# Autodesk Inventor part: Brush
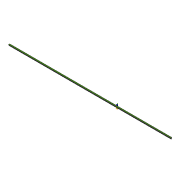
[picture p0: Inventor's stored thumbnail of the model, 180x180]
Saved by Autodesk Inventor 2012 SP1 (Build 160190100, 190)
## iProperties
Created: 2006-03
Part Number: Brush
Document SubType Name: Modeling
Material: Silicone
Mass: 8.74327 g
Surface Area: 94.4143 cm^2
Volume: 6.99461 cm^3
Density: 1.25 g/cm^3
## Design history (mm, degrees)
sketch "Sketch1"
  geometry: L1 (0, 0)-(-2.332, 5); L2 (-2.332, 5)-(2.332, 5); L3 (2.332, 5)-(0, 0)
  constraints: 6 end point, 1 equal length, 1 horizontal
  dimensions: "d0" = 5 distance from line of L2 L1.start; "d2" = 50 deg angle of L3 L1
extrude "Extrusion1" new body sketch "Sketch1" distance "d3" = 200; taper "d4" = 0 deg
extrude "Extrusion2" join sketch "Sketch1" distance "d5" = 400; taper "d6" = 0 deg
sketch "Sketch2"
  geometry: L1 (0, -1.25)-(0, 16.25) reference; L2 (-200, 5)-(400, 5) reference; C1 r 2.5 at (0, 10); 1 further point
  constraints: 1 centre point, 1 point on line
  dimensions: "d7" = 5 distance from line of C1.centre L2; "d8" = 5 diameter of C1
workaxis "Work Axis2"
workpoint "Work Point1"
body "Solid1"
